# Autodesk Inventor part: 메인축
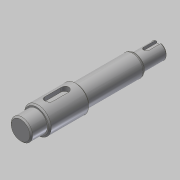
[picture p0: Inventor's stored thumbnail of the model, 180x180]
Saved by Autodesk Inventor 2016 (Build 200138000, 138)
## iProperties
Created: 2019-03
Part Number: 메인축
Material: 강철, 연강
Document SubType Name: Modeling
Designer: mduedu
Density: 1 g/cm^3
Appearance: 강철
Author: mduedu
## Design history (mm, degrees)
sketch "스케치1"
  geometry: L1 (0, 0)-(12, 0); L2 (12, 0)-(12, 8); L3 (12, 8)-(0, 8); L4 (0, 8)-(0, 0); L5 (12, 0)-(42, 0); L6 (42, 0)-(42, 10); L7 (42, 10)-(12, 10); L8 (12, 10)-(12, 0); L9 (42, 0)-(86, 0); L10 (86, 0)-(86, 8); L11 (86, 8)-(42, 8); L12 (42, 8)-(42, 0); L13 (86, 0)-(104, 0); L14 (104, 0)-(104, 6); L15 (104, 6)-(86, 6); L16 (86, 6)-(86, 0)
  constraints: 32 end point, 8 parallel, 4 horizontal, 4 perpendicular
  dimensions: "d0" = 16 diameter of L3 L1; "d2" = 20 diameter of L7 L5; "d3" = 16 diameter of L11 L9; "d4" = 12 diameter of L15 L13; "d5" = 12 distance of L2.end L3.end; "d6" = 30 distance of L6.end L7.end; "d7" = 86 distance between parallel lines of L10 L4; "d8" = 104 distance between parallel lines of L14 L4
revolve "회전1" sketch "스케치1" stored, may be unused: angle "d9" = 90 deg
node "작업 평면1"
sketch "스케치2" dims "d10" = 18
  geometry: L1 (6, -3)-(-6, -3); L2 (-6, -3)-(-6, 3); L3 (-6, 3)-(6, 3); L4 (6, 3)-(6, -3); L5 (15, 10)-(15, -10) reference; 3 further points
  constraints: 8 end point, 2 midpoint, 2 parallel, 2 vertical alignment, 1 horizontal, 1 horizontal alignment, 1 perpendicular, 4 other
  dimensions: "d12" = 6 distance between parallel lines of L3 L1; "d13" = 6 dimension on L5
extrude "돌출1" cut sketch "스케치2" distance "d14" = 3.5; taper "d15" = 0 deg
node "작업 평면2"
sketch "스케치3"
  geometry: L1 (-9, 6)-(-9, -6) reference; L2 (1, -2)-(-9, -2); L3 (1, 2)-(-9, 2); A1 r 2 centre (1, 0) between (1, -2) and (1, 2); 2 further points
  constraints: 4 end point, 2 point on circle, 2 point on line, 2 tangent, 1 centre point, 1 horizontal alignment, 1 midpoint, 1 parallel, 1 perpendicular
  dimensions: "d16" = 12 dimension on A1 L1; "d17" = 4 distance between parallel lines of L3 L2
extrude "돌출2" cut sketch "스케치3" distance "d18" = 2.5; taper "d19" = 0 deg
chamfer "모따기1" distance "d20" = 1; stored, may be unused: second distance "d21" = 2, angle "d22" = 45 deg
chamfer "모따기2" distance "d23" = 1; stored, may be unused: second distance "d24" = 2, angle "d25" = 45 deg
chamfer "모따기3" distance "d26" = 1.73; stored, may be unused: second distance "d27" = 2, angle "d28" = 30 deg
fillet "모깎기2" dims "d31" = 1, "d32" = 2
node "솔리드1"
